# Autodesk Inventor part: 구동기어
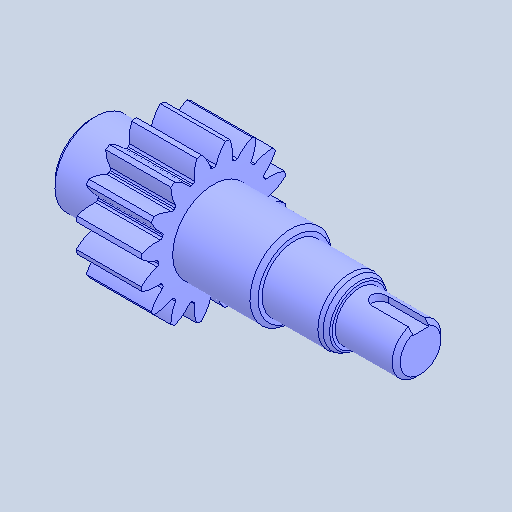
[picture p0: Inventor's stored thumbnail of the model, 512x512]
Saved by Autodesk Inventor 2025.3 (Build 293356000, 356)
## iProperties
Created: 2025-10
Part Number: 구동기어
Material: 강철, 합금
Document SubType Name: Modeling
Designer: PC-13
Density: 7.73 g/cm^3
Appearance: 기본값
Author: jhkim
Sending System: Autodesk Inventor 2026
Preprocessor: ST-DEVELOPER v20.1
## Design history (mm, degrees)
feature "솔리드1"
node "솔리드2"
